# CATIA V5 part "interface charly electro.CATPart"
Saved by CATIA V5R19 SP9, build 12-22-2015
Part number: interface charly electro
Bounding box of the stored display mesh (mm): x -200 to 200, y -123.5 to 123.5, z 0 to 19
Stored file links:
  Z:\charly_robot\interface charly electro.CATPart
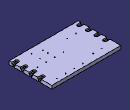
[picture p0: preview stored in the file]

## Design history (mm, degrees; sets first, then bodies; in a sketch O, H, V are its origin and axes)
AxisSystem1: origin (0, 0, 0), X (1, 0, 0), Y (0, 1, 0), Z (0, 0, 1)
Body1 (main body)
  Sketch1 on XY plane of AxisSystem1, origin (0, 0, 0), H (1, 0, 0), V (0, 1, 0)
    line L1 (200, 123.5) -> (200, -123.5)
    line L2 (200, -123.5) -> (-200, -123.5)
    line L3 (-200, -123.5) -> (-200, 123.5)
    line L4 (-200, 123.5) -> (200, 123.5)
    length L4 = 400
    length L1 = 247
    vertical: L1 V, L3 V
    horizontal: L2 H, L4 H
    equidistance: L1 L3 O, L2 L4 O
  Pad1: profile Sketch1, direction (0, 0, 1), length 19
  Sketch2 on start face of Pad1, origin (131.1733, -56.2905, 0), H (1, 0, 0), V (0, 1, 0)
    point P1 (-261.1733, 139.7905)
    reference intersected line E1 (-331.1733, 179.7905) -> (68.8267, 179.7905) from face of Pad1 from Sketch1.L4
    reference intersected line E2 (-331.1733, -67.2095) -> (-331.1733, 179.7905) from face of Pad1 from Sketch1.L3
    distance P1 E2 = 70
    distance P1 E1 = 40
  Hole1: placed by Sketch2, at (-130, 83.5, 0) direction (0, 0, 1), diameter 5, through (limit type 6), counterbore diameter 15, counterbore depth 15
  RectPattern1: of Hole1, direction 1 instances 2, spacing 50, along X axis, direction 2 instances 2, spacing 150, along Y axis reversed
  Sketch3 on start face of Pad1, origin (-179.7372, 103.0284, 0), H (1, 0, 0), V (0, 1, 0)
    point P1 (329.7372, 0.4716)
    reference intersected line E1 (-20.2628, 20.4716) -> (379.7372, 20.4716) from face of Pad1 from Sketch1.L4
    reference intersected line E2 (379.7372, 20.4716) -> (379.7372, -226.5284) from face of Pad1 from Sketch1.L1
    distance P1 E2 = 50
    distance P1 E1 = 20
  Hole2: placed by Sketch3, at (150, 103.5, 0) direction (0, 0, 1), diameter 5, through (limit type 6), counterbore diameter 15, counterbore depth 15
  RectPattern2: of Hole2, direction 1 instances 2, spacing 113, along Y axis reversed, direction 2 instances 4, spacing 50, along X axis reversed
  Sketch4 on start face of Pad1, origin (106.3433, -47.4661, 0), H (1, 0, 0), V (0, -1, 0)
    point P1 (-6.3433, 46.0339)
    reference intersected line E1 (93.6567, 76.0339) -> (93.6567, -170.9661) from face of Pad1 from Sketch1.L1
    reference intersected line E2 (-306.3433, 76.0339) -> (93.6567, 76.0339) from face of Pad1 from Sketch1.L2
    distance P1 E1 = 100
    distance P1 E2 = 30
  Hole3: placed by Sketch4, at (100, -93.5, 0) direction (0, 0, 1), diameter 5, through (limit type 6), counterbore diameter 15, counterbore depth 15
  Sketch5 on start face of Pad1, origin (155.7389, -35.6399, 0), H (1, 0, 0), V (0, -1, 0)
    point P1 (-55.7389, 9.8601)
    reference projected point E1 (-55.7389, 57.8601) from axis of face of Hole3
    reference projected point E2 (-55.7389, 57.8601) from axis of face of Hole3
    distance P1 E1 = 48
    distance P1 E2 H = 0
  Hole4: placed by Sketch5, at (100, -45.5, 0) direction (0, 0, 1), diameter 5, through (limit type 6), counterbore diameter 15, counterbore depth 15
  Sketch6 on start face of Pad1, origin (104.8923, -58.437, 0), H (1, 0, 0), V (0, -1, 0)
    point P1 (-55.3923, 19.563)
    reference projected point E1 (-4.8923, 35.063) from axis of face of Hole3
    reference projected point E2 (-4.8923, 35.063) from axis of face of Hole3
    distance E1 P1 H = 50.5
    distance E2 P1 V = 15.5
  Hole5: placed by Sketch6, at (49.5, -78, 0) direction (0, 0, 1), diameter 5, through (limit type 6), counterbore diameter 15, counterbore depth 15
  Sketch7 on start face of Pad1, origin (103.7745, -32.7621, 0), H (1, 0, 0), V (0, -1, 0)
    point P1 (-54.2745, 17.2379)
    reference projected point E1 (-3.7745, 60.7379) from axis of face of Hole3
    reference projected point E2 (-3.7745, 60.7379) from axis of face of Hole3
    distance E1 P1 H = 50.5
    distance E2 P1 V = 43.5
  Hole6: placed by Sketch7, at (49.5, -50, 0) direction (0, 0, 1), diameter 5, through (limit type 6), counterbore diameter 15, counterbore depth 15
  Sketch8 on end face of Pad1, origin (0, 0, 19), H (1, 0, 0), V (0, 1, 0)
    construction line L1 (-220, -98.5) -> (-180, -98.5)
    point P1 (-220, -98.5)
    point P2 (-180, -98.5)
    line L2 (-220, -94.5) -> (-180, -94.5)
    line L3 (-180, -102.5) -> (-220, -102.5)
    arc A1 centre (-180, -98.5) radius 4 from (-180, -94.5) to (-180, -102.5) cw
    arc A2 centre (-220, -98.5) radius 4 from (-220, -102.5) to (-220, -94.5) cw
    reference intersected line E1 (-200, -123.5) -> (-200, 123.5) from face of Pad1 from Sketch1.L3
    reference intersected line E2 (200, -123.5) -> (-200, -123.5) from face of Pad1 from Sketch1.L2
    distance L1 L2 = 4
    length L1 = 40
    distance L1 E2 = 25
    horizontal: L1 H
    tangency: A1 L2, A2 L2, A1 L3, A2 L3
    symmetry: P2 P1 E1
  Pocket1: profile Sketch8, direction (0, 0, -1), length 19
  Sketch9 on end face of Pad1, origin (0, 0, 19), H (1, 0, 0), V (0, 1, 0)
    construction line L1 (-220, -98.5) -> (-180, -98.5)
    point P2 (-180, -98.5)
    line L2 (-220, -88.5) -> (-180, -88.5)
    line L3 (-180, -108.5) -> (-220, -108.5)
    arc A1 centre (-180, -98.5) radius 10 from (-180, -88.5) to (-180, -108.5) cw
    arc A2 centre (-220, -98.5) radius 10 from (-220, -108.5) to (-220, -88.5) cw
    reference projected point E1 (-180, -98.5) from axis of face of Pocket1 from Sketch8.A1
    distance L1 L2 = 10
    length L1 = 40
    horizontal: L1 H
    tangency: A1 L2, A2 L2, A1 L3, A2 L3
    coincidence: P2 E1
  Pocket2: profile Sketch9, direction (0, 0, -1), length 9
  RectPattern3: of Pocket1, Pocket2, direction 1 instances 4, spacing 50, along Y axis, direction 2 instances 2, spacing 400, along X axis
  DatumCurve1 to DatumCurve3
